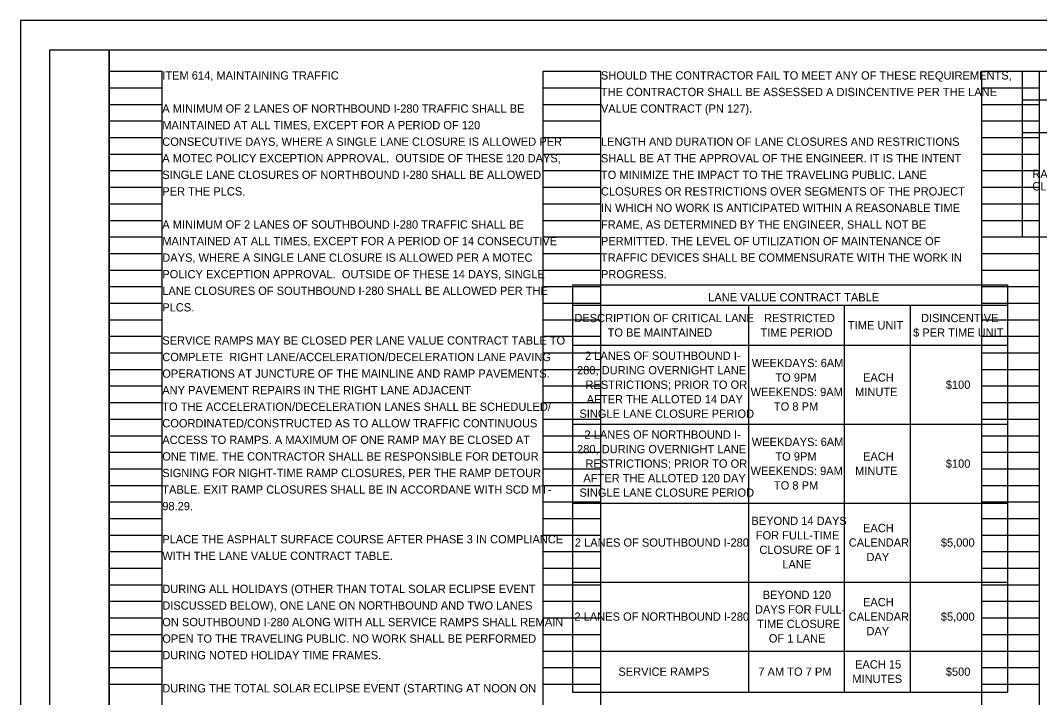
# Model space of a CAD drawing. Extents: x 0 to 34, y 0 to 22.
# Drawn here: x 0 to 17.24, y 10.55 to 22 of the extents above; entities that cross this region are included whole.
import ezdxf

# ---------------------------------------------------------------- set-up
doc = ezdxf.new("R2010")
doc.units = 0
for name, color, linetype in [('Default', 7, 'Continuous'), ('SH_Border', 7, 'Continuous'), ('SH_Cut_Line', 7, 'Continuous'), ('SH_Data', 7, 'Continuous'), ('SH_Text', 7, 'Continuous')]:
    doc.layers.add(name, color=color, linetype=linetype)

msp = doc.modelspace()

# ---------------------------------------------------------------- linework, layer by layer
at = {"layer": 'Default'}
for p, q in [((9.337, 17.53), (16.699, 17.53)), ((9.337, 17.53), (9.337, 10.645)), ((16.699, 17.53), (16.699, 10.645)), ((9.337, 17.184), (16.699, 17.184)), ((12.318, 17.184), (12.318, 10.645)), ((13.932, 17.184), (13.932, 10.645)), ((15.052, 17.184), (15.052, 10.645)), ((9.337, 16.509), (16.699, 16.509)), ((9.337, 15.175), (16.699, 15.175)), ((9.337, 13.841), (16.699, 13.841)), ((9.337, 12.506), (16.699, 12.506)), ((9.337, 11.337), (16.699, 11.337)), ((9.337, 10.645), (16.699, 10.645))]:
    msp.add_line(p, q, dxfattribs=at)
at = {"layer": 'SH_Border'}
for points in [[(0.5, 21.5), (1.5, 21.5), (1.5, 0.5), (0.5, 0.5)], [(1.5, 21.5), (33.5, 21.5), (33.5, 0.5), (1.5, 0.5)]]:
    msp.add_lwpolyline(points, close=True, dxfattribs=at)
at = {"layer": 'SH_Cut_Line'}
msp.add_lwpolyline([(0, 0), (34, 0), (34, 22), (0, 22)], close=True, dxfattribs=at)
at = {"layer": 'SH_Data'}
for p, q in [((1.5, 0.98), (1.5, 21.14)), ((1.5, 21.14), (2.4, 21.14)), ((2.4, 0.98), (2.4, 21.14)), ((8.84, 0.98), (8.84, 21.14)), ((8.84, 21.14), (9.82, 21.14)), ((9.82, 0.98), (9.82, 21.14)), ((16.26, 0.98), (16.26, 21.14)), ((16.26, 21.14), (17.24, 21.14)), ((17.24, 0.98), (17.24, 21.14)), ((1.5, 20.86), (2.4, 20.86)), ((8.84, 20.86), (9.82, 20.86)), ((16.26, 20.86), (17.24, 20.86)), ((1.5, 20.58), (2.4, 20.58)), ((8.84, 20.58), (9.82, 20.58)), ((16.26, 20.58), (17.24, 20.58)), ((1.5, 20.3), (2.4, 20.3)), ((8.84, 20.3), (9.82, 20.3)), ((16.26, 20.3), (17.24, 20.3)), ((1.5, 20.02), (2.4, 20.02)), ((8.84, 20.02), (9.82, 20.02)), ((16.26, 20.02), (17.24, 20.02)), ((1.5, 19.74), (2.4, 19.74)), ((8.84, 19.74), (9.82, 19.74)), ((16.26, 19.74), (17.24, 19.74)), ((1.5, 19.46), (2.4, 19.46)), ((8.84, 19.46), (9.82, 19.46)), ((16.26, 19.46), (17.24, 19.46)), ((1.5, 19.18), (2.4, 19.18)), ((8.84, 19.18), (9.82, 19.18)), ((16.26, 19.18), (17.24, 19.18)), ((1.5, 18.9), (2.4, 18.9)), ((8.84, 18.9), (9.82, 18.9)), ((16.26, 18.9), (17.24, 18.9)), ((1.5, 18.62), (2.4, 18.62)), ((8.84, 18.62), (9.82, 18.62)), ((16.26, 18.62), (17.24, 18.62)), ((1.5, 18.34), (2.4, 18.34)), ((8.84, 18.34), (9.82, 18.34)), ((16.26, 18.34), (17.24, 18.34)), ((1.5, 18.06), (2.4, 18.06)), ((8.84, 18.06), (9.82, 18.06)), ((16.26, 18.06), (17.24, 18.06)), ((1.5, 17.78), (2.4, 17.78)), ((8.84, 17.78), (9.82, 17.78)), ((16.26, 17.78), (17.24, 17.78)), ((1.5, 17.5), (2.4, 17.5)), ((8.84, 17.5), (9.82, 17.5)), ((16.26, 17.5), (17.24, 17.5)), ((1.5, 17.22), (2.4, 17.22)), ((8.84, 17.22), (9.82, 17.22)), ((16.26, 17.22), (17.24, 17.22)), ((1.5, 16.94), (2.4, 16.94)), ((8.84, 16.94), (9.82, 16.94)), ((16.26, 16.94), (17.24, 16.94)), ((1.5, 16.66), (2.4, 16.66)), ((8.84, 16.66), (9.82, 16.66)), ((16.26, 16.66), (17.24, 16.66)), ((1.5, 16.38), (2.4, 16.38)), ((8.84, 16.38), (9.82, 16.38)), ((16.26, 16.38), (17.24, 16.38)), ((1.5, 16.1), (2.4, 16.1)), ((8.84, 16.1), (9.82, 16.1)), ((16.26, 16.1), (17.24, 16.1)), ((1.5, 15.82), (2.4, 15.82)), ((8.84, 15.82), (9.82, 15.82)), ((16.26, 15.82), (17.24, 15.82)), ((1.5, 15.54), (2.4, 15.54)), ((8.84, 15.54), (9.82, 15.54)), ((16.26, 15.54), (17.24, 15.54)), ((1.5, 15.26), (2.4, 15.26)), ((8.84, 15.26), (9.82, 15.26)), ((16.26, 15.26), (17.24, 15.26)), ((1.5, 14.98), (2.4, 14.98)), ((8.84, 14.98), (9.82, 14.98)), ((16.26, 14.98), (17.24, 14.98)), ((1.5, 14.7), (2.4, 14.7)), ((8.84, 14.7), (9.82, 14.7)), ((16.26, 14.7), (17.24, 14.7)), ((1.5, 14.42), (2.4, 14.42)), ((8.84, 14.42), (9.82, 14.42)), ((16.26, 14.42), (17.24, 14.42)), ((1.5, 14.14), (2.4, 14.14)), ((8.84, 14.14), (9.82, 14.14)), ((16.26, 14.14), (17.24, 14.14)), ((1.5, 13.86), (2.4, 13.86)), ((8.84, 13.86), (9.82, 13.86)), ((16.26, 13.86), (17.24, 13.86)), ((1.5, 13.58), (2.4, 13.58)), ((8.84, 13.58), (9.82, 13.58)), ((16.26, 13.58), (17.24, 13.58)), ((1.5, 13.3), (2.4, 13.3)), ((8.84, 13.3), (9.82, 13.3)), ((16.26, 13.3), (17.24, 13.3)), ((1.5, 13.02), (2.4, 13.02)), ((8.84, 13.02), (9.82, 13.02)), ((16.26, 13.02), (17.24, 13.02)), ((1.5, 12.74), (2.4, 12.74)), ((8.84, 12.74), (9.82, 12.74)), ((16.26, 12.74), (17.24, 12.74)), ((1.5, 12.46), (2.4, 12.46)), ((8.84, 12.46), (9.82, 12.46)), ((16.26, 12.46), (17.24, 12.46)), ((1.5, 12.18), (2.4, 12.18)), ((8.84, 12.18), (9.82, 12.18)), ((16.26, 12.18), (17.24, 12.18)), ((1.5, 11.9), (2.4, 11.9)), ((8.84, 11.9), (9.82, 11.9)), ((16.26, 11.9), (17.24, 11.9)), ((1.5, 11.62), (2.4, 11.62)), ((8.84, 11.62), (9.82, 11.62)), ((16.26, 11.62), (17.24, 11.62)), ((1.5, 11.34), (2.4, 11.34)), ((8.84, 11.34), (9.82, 11.34)), ((16.26, 11.34), (17.24, 11.34)), ((1.5, 11.06), (2.4, 11.06)), ((8.84, 11.06), (9.82, 11.06)), ((16.26, 11.06), (17.24, 11.06)), ((1.5, 10.78), (2.4, 10.78)), ((8.84, 10.78), (9.82, 10.78)), ((16.26, 10.78), (17.24, 10.78))]:
    msp.add_line(p, q, dxfattribs=at)
at = {"layer": 'SH_Text'}
for p, q in [((16.947, 21.14), (16.947, 18.34)), ((16.947, 21.14), (23.966, 21.14)), ((16.947, 20.66), (23.966, 20.66)), ((16.947, 20.106), (23.966, 20.106)), ((16.947, 18.34), (23.966, 18.34))]:
    msp.add_line(p, q, dxfattribs=at)

# ---------------------------------------------------------------- texts
at = {"layer": 'Default'}
for s, p in [('LANE VALUE CONTRACT TABLE', (11.634, 17.25)), ('DESCRIPTION OF CRITICAL LANE ', (9.371, 16.899)), ('RESTRICTED ', (12.58, 16.899)), ('TIME UNIT', (13.997, 16.776)), ('DISINCENTIVE ', (15.234, 16.899)), ('TO BE MAINTAINED', (9.933, 16.654)), ('TIME PERIOD', (12.52, 16.654)), ('$ PER TIME UNIT', (15.1, 16.654)), ('2 LANES OF SOUTHBOUND I-', (9.55, 16.262)), ('WEEKDAYS: 6AM ', (12.371, 16.139)), ('280, DURING OVERNIGHT LANE ', (9.416, 16.017)), ('TO 9PM', (12.771, 15.894)), ('EACH ', (14.253, 15.894)), ('RESTRICTIONS; PRIOR TO OR ', (9.558, 15.772)), ('$100', (15.653, 15.772)), ('WEEKENDS: 9AM ', (12.352, 15.649)), ('MINUTE', (14.119, 15.649)), ('AFTER THE ALLOTED 14 DAY ', (9.579, 15.527)), ('TO 8 PM', (12.746, 15.404)), ('SINGLE LANE CLOSURE PERIOD', (9.456, 15.282)), ('2 LANES OF NORTHBOUND I-', (9.542, 14.928)), ('WEEKDAYS: 6AM ', (12.371, 14.805)), ('280, DURING OVERNIGHT LANE ', (9.416, 14.683)), ('TO 9PM', (12.771, 14.56)), ('EACH ', (14.253, 14.56)), ('RESTRICTIONS; PRIOR TO OR ', (9.558, 14.438)), ('$100', (15.653, 14.438)), ('AFTER THE ALLOTED 120 DAY ', (9.523, 14.193)), ('WEEKENDS: 9AM ', (12.352, 14.315)), ('MINUTE', (14.119, 14.315)), ('TO 8 PM', (12.746, 14.07)), ('SINGLE LANE CLOSURE PERIOD', (9.456, 13.948)), ('BEYOND 14 DAYS ', (12.365, 13.471)), ('EACH ', (14.253, 13.349)), ('FOR FULL-TIME ', (12.439, 13.226)), ('2 LANES OF SOUTHBOUND I-280', (9.379, 13.104)), ('CLOSURE OF 1 ', (12.5, 12.981)), ('CALENDAR ', (14.012, 13.104)), ('$5,000', (15.569, 13.104)), ('DAY', (14.311, 12.859)), ('LANE', (12.888, 12.736)), ('BEYOND 120 ', (12.557, 12.219)), ('DAYS FOR FULL-', (12.426, 11.974)), ('EACH ', (14.253, 12.097)), ('2 LANES OF NORTHBOUND I-280', (9.372, 11.852)), ('CALENDAR ', (14.012, 11.852)), ('$5,000', (15.569, 11.852)), ('TIME CLOSURE ', (12.462, 11.729)), ('DAY', (14.311, 11.607)), ('OF 1 LANE', (12.66, 11.484)), ('SERVICE RAMPS', (10.115, 10.921)), ('7 AM TO 7 PM', (12.482, 10.921)), ('EACH 15 ', (14.118, 11.044)), ('$500', (15.653, 10.921)), ('MINUTES', (14.072, 10.799))]:
    msp.add_text(s, height=0.14, dxfattribs=at).set_placement(p)
at = {"layer": 'SH_Text'}
for s, p in [('ITEM 614, MAINTAINING TRAFFIC', (2.4, 21)), ('SHOULD THE CONTRACTOR FAIL TO MEET ANY OF THESE REQUIREMENTS,', (9.82, 21)), ('THE CONTRACTOR SHALL BE ASSESSED A DISINCENTIVE PER THE LANE', (9.82, 20.72)), ('A MINIMUM OF 2 LANES OF NORTHBOUND I-280 TRAFFIC SHALL BE ', (2.4, 20.44)), ('VALUE CONTRACT (PN 127).', (9.82, 20.44)), ('MAINTAINED AT ALL TIMES, EXCEPT FOR A PERIOD OF 120 ', (2.4, 20.16)), ('CONSECUTIVE DAYS, WHERE A SINGLE LANE CLOSURE IS ALLOWED PER ', (2.4, 19.88)), ('LENGTH AND DURATION OF LANE CLOSURES AND RESTRICTIONS', (9.82, 19.88)), ('A MOTEC POLICY EXCEPTION APPROVAL.  OUTSIDE OF THESE 120 DAYS, ', (2.4, 19.6)), ('SHALL BE AT THE APPROVAL OF THE ENGINEER. IT IS THE INTENT', (9.82, 19.6)), ('SINGLE LANE CLOSURES OF NORTHBOUND I-280 SHALL BE ALLOWED ', (2.4, 19.32)), ('TO MINIMIZE THE IMPACT TO THE TRAVELING PUBLIC. LANE', (9.82, 19.32)), ('RAMP & ROAD', (17.117, 19.335)), ('PER THE PLCS. ', (2.4, 19.04)), ('CLOSURES OR RESTRICTIONS OVER SEGMENTS OF THE PROJECT', (9.82, 19.04)), ('CLOSURES', (17.117, 19.125)), ('IN WHICH NO WORK IS ANTICIPATED WITHIN A REASONABLE TIME', (9.82, 18.76)), ('A MINIMUM OF 2 LANES OF SOUTHBOUND I-280 TRAFFIC SHALL BE ', (2.4, 18.48)), ('FRAME, AS DETERMINED BY THE ENGINEER, SHALL NOT BE', (9.82, 18.48)), ('MAINTAINED AT ALL TIMES, EXCEPT FOR A PERIOD OF 14 CONSECUTIVE ', (2.4, 18.2)), ('PERMITTED. THE LEVEL OF UTILIZATION OF MAINTENANCE OF', (9.82, 18.2)), ('DAYS, WHERE A SINGLE LANE CLOSURE IS ALLOWED PER A MOTEC ', (2.4, 17.92)), ('TRAFFIC DEVICES SHALL BE COMMENSURATE WITH THE WORK IN', (9.82, 17.92)), ('POLICY EXCEPTION APPROVAL.  OUTSIDE OF THESE 14 DAYS, SINGLE ', (2.4, 17.64)), ('PROGRESS.', (9.82, 17.64)), ('LANE CLOSURES OF SOUTHBOUND I-280 SHALL BE ALLOWED PER THE ', (2.4, 17.36)), ('PLCS. ', (2.4, 17.08)), ('SERVICE RAMPS MAY BE CLOSED PER LANE VALUE CONTRACT TABLE TO ', (2.4, 16.52)), ('COMPLETE  RIGHT LANE/ACCELERATION/DECELERATION LANE PAVING ', (2.4, 16.24)), ('OPERATIONS AT JUNCTURE OF THE MAINLINE AND RAMP PAVEMENTS.  ', (2.4, 15.96)), ('ANY PAVEMENT REPAIRS IN THE RIGHT LANE ADJACENT', (2.4, 15.68)), ('TO THE ACCELERATION/DECELERATION LANES SHALL BE SCHEDULED/', (2.4, 15.4)), ('COORDINATED/CONSTRUCTED AS TO ALLOW TRAFFIC CONTINUOUS', (2.4, 15.12)), ('ACCESS TO RAMPS. A MAXIMUM OF ONE RAMP MAY BE CLOSED AT ', (2.4, 14.84)), ('ONE TIME. THE CONTRACTOR SHALL BE RESPONSIBLE FOR DETOUR ', (2.4, 14.56)), ('SIGNING FOR NIGHT-TIME RAMP CLOSURES, PER THE RAMP DETOUR ', (2.4, 14.28)), ('TABLE. EXIT RAMP CLOSURES SHALL BE IN ACCORDANE WITH SCD MT-', (2.4, 14)), ('98.29.', (2.4, 13.72)), ('PLACE THE ASPHALT SURFACE COURSE AFTER PHASE 3 IN COMPLIANCE ', (2.4, 13.16)), ('WITH THE LANE VALUE CONTRACT TABLE. ', (2.4, 12.88)), ('DURING ALL HOLIDAYS (OTHER THAN TOTAL SOLAR ECLIPSE EVENT', (2.4, 12.32)), ('DISCUSSED BELOW), ONE LANE ON NORTHBOUND AND TWO LANES', (2.4, 12.04)), ('ON SOUTHBOUND I-280 ALONG WITH ALL SERVICE RAMPS SHALL REMAIN', (2.4, 11.76)), ('OPEN TO THE TRAVELING PUBLIC. NO WORK SHALL BE PERFORMED', (2.4, 11.48)), ('DURING NOTED HOLIDAY TIME FRAMES.', (2.4, 11.2)), ('DURING THE TOTAL SOLAR ECLIPSE EVENT (STARTING AT NOON ON', (2.4, 10.64))]:
    msp.add_text(s, height=0.14, dxfattribs=at).set_placement(p)

doc.saveas('drawing.dxf')
